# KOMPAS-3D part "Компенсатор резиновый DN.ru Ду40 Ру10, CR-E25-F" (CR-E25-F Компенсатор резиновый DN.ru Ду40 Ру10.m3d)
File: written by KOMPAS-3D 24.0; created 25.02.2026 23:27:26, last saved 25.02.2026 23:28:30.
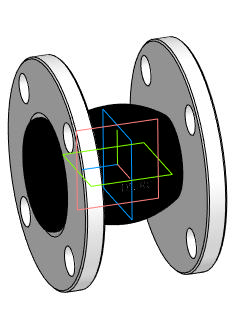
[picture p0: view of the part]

Document properties: Автор: DN.RU; Полное имя файла: D:\PROJECT CAD\DN.RU\...178(4)(ACTUALE). CR-E25-F Компенсатор резиновый DN.ru Ру10-16\DN40_PN10\CR-E25-F Компенсатор резиновый DN.ru Ду40 Ру10.m3d

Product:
- Body: Твердое тело2  | qty 1
    Масса: 3.467288
- Part/product: Компенсатор резиновый DN.ru Ду40 Ру10  | designation CR-E25-F
    Масса: 3.68
    Раздел спецификации: Прочие изделия
    Комментарий: D140-02161
    Примечание: D140-02161
    additional columns: Типовые

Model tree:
1. Твердое тело2  (labels: Твердое тело2)

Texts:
  CR-E25-F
